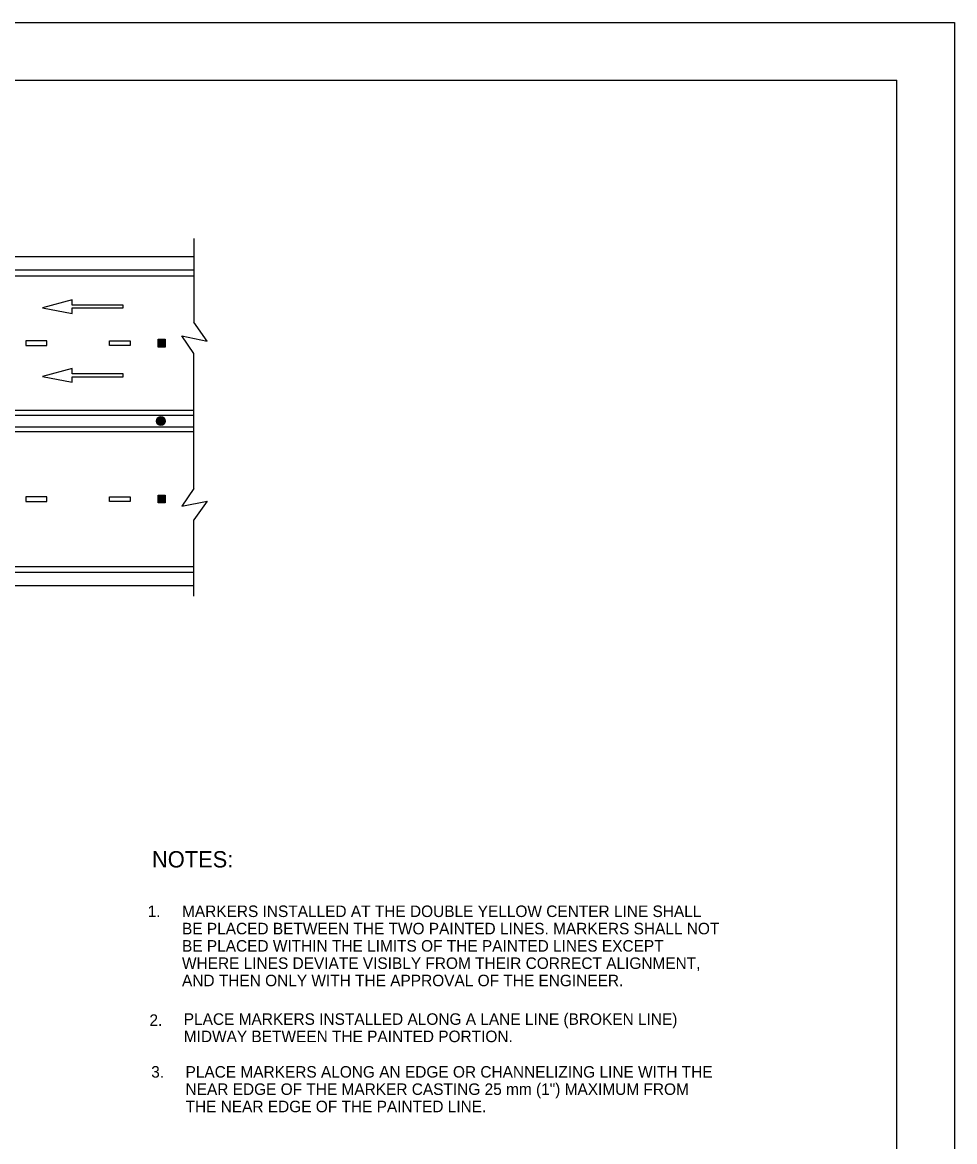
# Model space of a CAD drawing. Extents: x 639362 to 641108, y 298458 to 299646.
# Drawn here: x 640801.8 to 641044.3, y 299354.5 to 299645.6 of the extents above; entities that cross this region are included whole.
import ezdxf

# ---------------------------------------------------------------- set-up
doc = ezdxf.new("R2010")
doc.units = 0
for name, color, linetype in [('1', 7, 'Continuous'), ('2', 7, 'Continuous'), ('PLT-BNDY', 7, 'Continuous')]:
    doc.layers.add(name, color=color, linetype=linetype)

msp = doc.modelspace()

# ---------------------------------------------------------------- linework, layer by layer
at = {"layer": '1'}
for p in [(640243.31, 299630.63), (641029.31, 299066.63)]:
    msp.add_line(p, (641029.31, 299630.63), dxfattribs=at)
at = {"layer": '2'}
for p, q in [((640846.38, 299589.45), (640846.38, 299567.63)), ((640568.94, 299584.74), (640846.38, 299584.74)), ((640568.94, 299581.24), (640846.38, 299581.24)), ((640568.94, 299579.74), (640846.38, 299579.74)), ((640814.73, 299573.5), (640807.01, 299571.38)), ((640807.01, 299571.38), (640814.81, 299569.91)), ((640814.73, 299572.06), (640814.73, 299573.5)), ((640828.06, 299572.06), (640814.73, 299572.06)), ((640814.81, 299569.91), (640814.81, 299571.35)), ((640814.81, 299571.35), (640828.06, 299571.35)), ((640828.06, 299571.35), (640828.06, 299572.06)), ((640849.87, 299562.73), (640846.38, 299567.63)), ((640808.14, 299562.81), (640802.7, 299562.81)), ((640802.7, 299562.81), (640802.7, 299561.61)), ((640808.14, 299561.61), (640808.14, 299562.81)), ((640824.45, 299561.61), (640824.45, 299562.81)), ((640824.45, 299562.81), (640829.89, 299562.81)), ((640829.89, 299562.81), (640829.89, 299561.61)), ((640837.16, 299563.23), (640838.93, 299563.23)), ((640837.16, 299561.19), (640837.16, 299563.23)), ((640837.33, 299563.05), (640838.75, 299563.05)), ((640837.33, 299561.36), (640837.33, 299563.05)), ((640837.51, 299562.87), (640838.58, 299562.87)), ((640837.51, 299561.54), (640837.51, 299562.87)), ((640837.69, 299561.72), (640837.69, 299562.69)), ((640837.69, 299562.69), (640838.4, 299562.69)), ((640837.87, 299562.52), (640838.22, 299562.52)), ((640837.87, 299561.9), (640837.87, 299562.52)), ((640838.04, 299562.34), (640838.04, 299562.07)), ((640838.22, 299562.52), (640838.22, 299561.9)), ((640838.4, 299562.69), (640838.4, 299561.72)), ((640838.58, 299562.87), (640838.58, 299561.54)), ((640838.75, 299563.05), (640838.75, 299561.36)), ((640838.93, 299563.23), (640838.93, 299561.19)), ((640846.38, 299559.5), (640843.33, 299564.08)), ((640843.33, 299564.08), (640849.87, 299562.73)), ((640802.7, 299561.61), (640808.14, 299561.61)), ((640829.89, 299561.61), (640824.45, 299561.61)), ((640838.93, 299561.19), (640837.16, 299561.19)), ((640838.75, 299561.36), (640837.33, 299561.36)), ((640838.58, 299561.54), (640837.51, 299561.54)), ((640838.4, 299561.72), (640837.69, 299561.72)), ((640838.22, 299561.9), (640837.87, 299561.9)), ((640846.38, 299524.36), (640846.38, 299559.5)), ((640814.73, 299555.62), (640807.01, 299553.51)), ((640807.01, 299553.51), (640814.81, 299552.03)), ((640814.73, 299554.18), (640814.73, 299555.62)), ((640828.06, 299554.18), (640814.73, 299554.18)), ((640814.81, 299552.03), (640814.81, 299553.47)), ((640814.81, 299553.47), (640828.06, 299553.47)), ((640828.06, 299553.47), (640828.06, 299554.18)), ((640846.38, 299544.68), (640568.94, 299544.68)), ((640846.38, 299543.48), (640846.38, 299544.68)), ((640568.94, 299543.48), (640846.38, 299543.48)), ((640846.38, 299540.38), (640568.94, 299540.38)), ((640568.94, 299539.18), (640846.38, 299539.18)), ((640846.38, 299539.18), (640846.38, 299540.38)), ((640846.38, 299524.36), (640843.33, 299519.78)), ((640808.14, 299522.25), (640802.7, 299522.25)), ((640802.7, 299522.25), (640802.7, 299521.05)), ((640808.14, 299521.05), (640808.14, 299522.25)), ((640824.45, 299521.05), (640824.45, 299522.25)), ((640824.45, 299522.25), (640829.89, 299522.25)), ((640829.89, 299522.25), (640829.89, 299521.05)), ((640837.16, 299522.67), (640838.93, 299522.67)), ((640837.16, 299520.63), (640837.16, 299522.67)), ((640837.33, 299522.49), (640838.75, 299522.49)), ((640837.33, 299520.81), (640837.33, 299522.49)), ((640837.51, 299522.31), (640838.58, 299522.31)), ((640837.51, 299520.98), (640837.51, 299522.31)), ((640837.69, 299521.16), (640837.69, 299522.14)), ((640837.69, 299522.14), (640838.4, 299522.14)), ((640837.87, 299521.96), (640838.22, 299521.96)), ((640837.87, 299521.34), (640837.87, 299521.96)), ((640838.22, 299521.34), (640837.87, 299521.34)), ((640838.04, 299521.78), (640838.04, 299521.51)), ((640838.22, 299521.96), (640838.22, 299521.34)), ((640838.4, 299522.14), (640838.4, 299521.16)), ((640838.58, 299522.31), (640838.58, 299520.98)), ((640838.75, 299522.49), (640838.75, 299520.81)), ((640838.93, 299522.67), (640838.93, 299520.63)), ((640802.7, 299521.05), (640808.14, 299521.05)), ((640829.89, 299521.05), (640824.45, 299521.05)), ((640838.93, 299520.63), (640837.16, 299520.63)), ((640838.75, 299520.81), (640837.33, 299520.81)), ((640838.58, 299520.98), (640837.51, 299520.98)), ((640838.4, 299521.16), (640837.69, 299521.16)), ((640843.33, 299519.78), (640849.87, 299521.13)), ((640849.87, 299521.13), (640846.38, 299516.24)), ((640846.38, 299496.39), (640846.38, 299516.24)), ((640568.94, 299504.12), (640846.38, 299504.12)), ((640568.94, 299502.62), (640846.38, 299502.62)), ((640568.94, 299499.12), (640846.38, 299499.12))]:
    msp.add_line(p, q, dxfattribs=at)
for radius in [1.15, 1.07, 0.985, 0.904, 0.822, 0.741, 0.659, 0.578, 0.496, 0.414, 0.333, 0.251, 0.17, 0.0881]:
    msp.add_circle((640837.85, 299541.93), radius, dxfattribs=at)
at = {"layer": 'PLT-BNDY'}
msp.add_lwpolyline([(640203.31, 299645.63), (641044.31, 299645.63), (641044.31, 299051.63), (640203.31, 299051.63)], close=True, dxfattribs=at)

# ---------------------------------------------------------------- texts
at = {"layer": '2'}
for s, height, p in [('NOTES:', 4.25, (640835.53, 299425.82)), ('1. ', 3, (640834.41, 299412.93)), ('MARKERS INSTALLED AT THE DOUBLE YELLOW CENTER LINE SHALL', 3, (640843.34, 299412.93)), ('BE PLACED BETWEEN THE TWO PAINTED LINES. MARKERS SHALL NOT', 3, (640843.34, 299408.43)), ('BE PLACED WITHIN THE LIMITS OF THE PAINTED LINES EXCEPT', 3, (640843.34, 299403.93)), ('WHERE LINES DEVIATE VISIBLY FROM THEIR CORRECT ALIGNMENT,', 3, (640843.34, 299399.43)), ('AND THEN ONLY WITH THE APPROVAL OF THE ENGINEER.', 3, (640843.34, 299394.93)), ('2. ', 3, (640834.87, 299384.61)), ('PLACE MARKERS INSTALLED ALONG A LANE LINE (BROKEN LINE)', 3, (640843.8, 299384.89)), ('MIDWAY BETWEEN THE PAINTED PORTION.', 3, (640843.8, 299380.39)), ('3. ', 3, (640835.33, 299371.16)), ('PLACE MARKERS ALONG AN EDGE OR CHANNELIZING LINE WITH THE', 3, (640844.26, 299371.16)), ('NEAR EDGE OF THE MARKER CASTING 25 mm (1") MAXIMUM FROM ', 3, (640844.26, 299366.66)), ('THE NEAR EDGE OF THE PAINTED LINE.', 3, (640844.26, 299362.16))]:
    msp.add_text(s, height=height, dxfattribs=at).set_placement(p)

doc.saveas('drawing.dxf')
